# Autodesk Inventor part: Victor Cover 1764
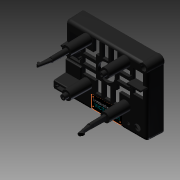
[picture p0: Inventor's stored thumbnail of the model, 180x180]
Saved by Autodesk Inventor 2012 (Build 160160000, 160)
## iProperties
Shininess: 64.0
Length Units: 11272
Angle Units: 11279
Time Units: 11290
Mass Units: 11286
Length Display Precision: 3
Angle Display Precision: 2
Compacted: True
Part Number: Victor Cover 1764
Document SubType Name: Modeling
Created: 2007-01
Designer: uidk0133
Density: 1 g/cm^3
Material: Default
Density: 0.0
Volumn: 0.0
Area: 0.0
PropertySet Name: Model Information
Control State: 0
Master: False
Checked Out: False
Translation Standard: STEP AP203
File Name: V883-002 RevH.stp
Preprocessor: THINKDESIGN
Postprocessor: Build: Release: 6 RTM Build: 90b - Date: Tue 09/24/2002
Sent Units: INCHES
Uncertainty: 0.0
Author: uidk0133
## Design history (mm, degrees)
feature "Base1"
sketch "Label"
  geometry: L1 (22.225, 0)-(0, 0) reference; L2 (-1.905, -1.905)-(-1.905, -8.89) reference; L3 (0, -10.795)-(22.225, -10.795) reference; L4 (24.13, -8.89)-(24.13, -1.905) reference; L5 (-1.905, 0)-(24.13, 0); L6 (24.13, 0)-(24.13, -11.121); L7 (24.13, -11.121)-(-1.905, -11.121); L8 (-1.905, -11.121)-(-1.905, 0); L9 (-1.905, -1.905)-(-1.905, -8.89) reference; L10 (24.13, -8.89)-(24.13, -1.905) reference; L11 (22.225, 0)-(0, 0) reference; A1 r 1.905 centre (22.225, -1.905) between (24.13, -1.905) and (22.225, 0) reference; A2 r 1.905 centre (0, -1.905) between (0, 0) and (-1.905, -1.905) reference; A3 r 1.905 centre (0, -8.89) between (-1.905, -8.89) and (0, -10.795) reference; A4 r 1.905 centre (22.225, -8.89) between (22.225, -10.795) and (24.13, -8.89) reference; 1 other entity
  constraints: 3 collinear, 2 other
  node "Image2"
body "Solid1"
